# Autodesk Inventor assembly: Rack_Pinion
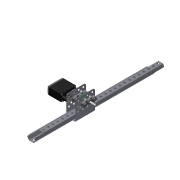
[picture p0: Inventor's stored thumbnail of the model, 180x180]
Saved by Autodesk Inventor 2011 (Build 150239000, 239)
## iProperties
Created: 2008-04
Part Number: Rack_Pinion
Document SubType Name: Assembly
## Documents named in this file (10)
- C:\Data Folder\VEX 2011\Inventor Datasets\Unit 7\Rack_Pinion.iam
- C:\Data Folder\VEX 2011\Inventor Datasets\Unit 7\Components\VL-RACK-BRK RevA.ipt
- C:\Data Folder\VEX 2011\Inventor Datasets\Unit 7\Components\VL-SLIDE-O-25 RevA.ipt
- C:\Data Folder\VEX 2011\Inventor Datasets\Unit 7\Components\VL-SLIDE-I-25 RevA.ipt
- C:\Data Folder\VEX 2011\Inventor Datasets\Unit 7\Components\BEARING-FLAT.ipt
- C:\Data Folder\VEX 2011\Inventor Datasets\Unit 7\Components\BEARING-RIVET.ipt
- C:\Data Folder\VEX 2011\Inventor Datasets\Unit 7\Components\VEX_Motor.iam
- C:\Data Folder\VEX 2011\Inventor Datasets\Unit 7\Components\VEX-12-TOOTH-GEAR.ipt
- C:\Data Folder\VEX 2011\Inventor Datasets\Unit 7\Components\Shaft_Collar.iam
- C:\Data Folder\VEX 2011\Inventor Datasets\Unit 7\Components\SHAFT-2000.ipt
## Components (13 placed, 9 different names)
1. VL-SLIDE-O-25 RevA:1 — Mate:1, Mate:2, Mate:3, Mate:4, Flush:1, Drive Me
2. VL-RACK-BRK RevA:1 — Mate:1, Mate:2, Flush:1, Mate:5, Mate:6, Mate:7, Mate:8, Mate:9, Mate:14, Mate:15, Mate:16, Mate:17, Flush:2
3. VL-SLIDE-I-25 RevA:1 — Mate:3, Mate:4, Flush:2, Mate:22, Drive Me
4. BEARING-FLAT:1 — Mate:8, Mate:9, Mate:14
5. BEARING-FLAT:2 — Mate:5, Mate:6, Mate:7, Insert:1, Insert:2
6. BEARING-RIVET:1
7. BEARING-RIVET:2
8. BEARING-RIVET:3 — Insert:1
9. BEARING-RIVET:4 — Insert:2
10. VEX_Motor:1 [sub-assembly] — Mate:15, Mate:16, Mate:17, Mate:24, Mate:25, Mate:26
11. SHAFT-2000:1 — Mate:24, Mate:25, Mate:26, Mate:27, Angle:1
12. VEX-12-TOOTH-GEAR:1 — Mate:22, Mate:23, Mate:27, Angle:1
13. Shaft_Collar:1 [sub-assembly] — Mate:23
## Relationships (25: Mate 19, Flush 3, Insert 2, Angle 1)
- Mate:1: VL-SLIDE-O-25 RevA:1 ↔ VL-RACK-BRK RevA:1
- Mate:2: VL-SLIDE-O-25 RevA:1 ↔ VL-RACK-BRK RevA:1
- Mate:3: VL-SLIDE-O-25 RevA:1 ↔ VL-SLIDE-I-25 RevA:1
- Mate:4: VL-SLIDE-O-25 RevA:1 ↔ VL-SLIDE-I-25 RevA:1
- Flush:1: VL-SLIDE-O-25 RevA:1 ↔ VL-RACK-BRK RevA:1
- Mate:5: VL-RACK-BRK RevA:1 ↔ BEARING-FLAT:2
- Mate:6: VL-RACK-BRK RevA:1 ↔ BEARING-FLAT:2
- Mate:7: VL-RACK-BRK RevA:1 ↔ BEARING-FLAT:2
- Mate:8: VL-RACK-BRK RevA:1 ↔ BEARING-FLAT:1
- Mate:9: VL-RACK-BRK RevA:1 ↔ BEARING-FLAT:1
- Insert:1: BEARING-FLAT:2 ↔ BEARING-RIVET:3
- Insert:2: BEARING-FLAT:2 ↔ BEARING-RIVET:4
- Mate:14: VL-RACK-BRK RevA:1 ↔ BEARING-FLAT:1
- Mate:15: VL-RACK-BRK RevA:1 ↔ VEX_Motor:1
- Mate:16: VL-RACK-BRK RevA:1 ↔ VEX_Motor:1
- Mate:17: VL-RACK-BRK RevA:1 ↔ VEX_Motor:1
- Flush:2: VL-RACK-BRK RevA:1 ↔ VL-SLIDE-I-25 RevA:1
- Mate:22: VL-SLIDE-I-25 RevA:1 ↔ VEX-12-TOOTH-GEAR:1
- Mate:23: VEX-12-TOOTH-GEAR:1 ↔ Shaft_Collar:1
- Mate:24: VEX_Motor:1 ↔ SHAFT-2000:1
- Mate:25: VEX_Motor:1 ↔ SHAFT-2000:1
- Mate:26: VEX_Motor:1 ↔ SHAFT-2000:1
- Mate:27: SHAFT-2000:1 ↔ VEX-12-TOOTH-GEAR:1
- Angle:1: SHAFT-2000:1 ↔ VEX-12-TOOTH-GEAR:1
- Drive Me [Flush]: VL-SLIDE-O-25 RevA:1 ↔ VL-SLIDE-I-25 RevA:1
